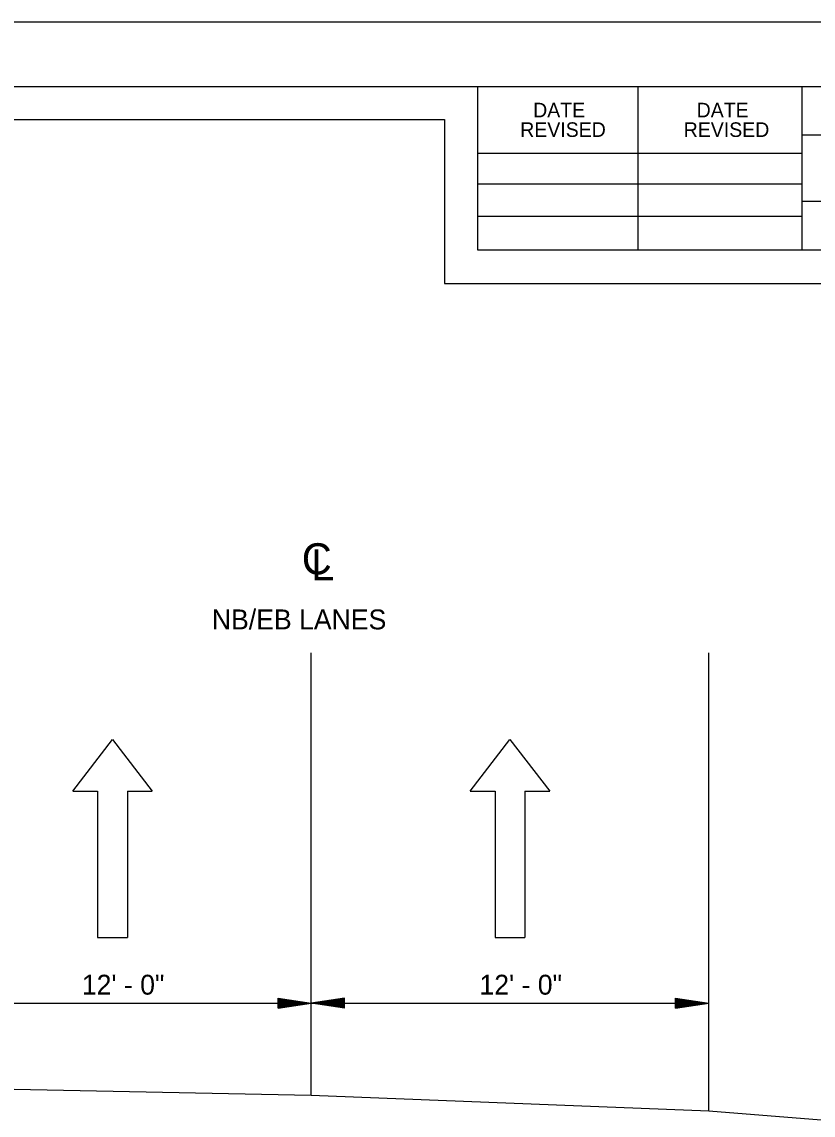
# Model space of a CAD drawing. Extents: x 1373889 to 1374222, y 382002 to 382215.
# Drawn here: x 1374127 to 1374174.7, y 382149.1 to 382215 of the extents above; entities that cross this region are included whole.
import ezdxf

# ---------------------------------------------------------------- set-up
doc = ezdxf.new("R2010")
doc.units = 0
for name, color, linetype in [('R_Border', 7, 'Continuous'), ('R_Draft', 7, 'Continuous'), ('R_No Plot', 7, 'Continuous'), ('R_Striping', 7, 'Continuous')]:
    doc.layers.add(name, color=color, linetype=linetype)

msp = doc.modelspace()

# ---------------------------------------------------------------- linework, layer by layer
at = {"layer": 'R_Border'}
for p, q in [((1373900.915, 382211.115), (1374217.095, 382211.115)), ((1374154.455, 382201.235), (1374154.455, 382211.115)), ((1374164.135, 382201.235), (1374164.135, 382211.115)), ((1374173.995, 382211.115), (1374173.995, 382201.235)), ((1374217.095, 382208.175), (1374173.995, 382208.175)), ((1374154.455, 382207.095), (1374173.995, 382207.095)), ((1374154.455, 382205.235), (1374173.995, 382205.235)), ((1374217.095, 382204.175), (1374173.995, 382204.175)), ((1374154.455, 382203.295), (1374173.995, 382203.295)), ((1374217.095, 382201.235), (1374154.455, 382201.235))]:
    msp.add_line(p, q, dxfattribs=at)
at = {"layer": 'R_Draft'}
for p, q in [((1374144.407, 382150.286), (1374144.407, 382176.948)), ((1374168.387, 382149.326), (1374168.387, 382176.948)), ((1374120.426, 382155.836), (1374144.407, 382155.836)), ((1374142.407, 382156.136), (1374144.407, 382155.836)), ((1374142.407, 382155.536), (1374142.407, 382156.136)), ((1374142.407, 382156.086), (1374144.073, 382155.836)), ((1374142.407, 382156.035), (1374143.729, 382155.836)), ((1374142.407, 382155.985), (1374143.396, 382155.836)), ((1374142.407, 382155.934), (1374143.057, 382155.836)), ((1374142.407, 382155.883), (1374142.723, 382155.836)), ((1374142.407, 382155.536), (1374144.407, 382155.836)), ((1374142.407, 382155.739), (1374143.057, 382155.836)), ((1374142.407, 382155.637), (1374143.729, 382155.836)), ((1374142.407, 382155.586), (1374144.073, 382155.836)), ((1374142.407, 382155.687), (1374143.396, 382155.836)), ((1374142.407, 382155.789), (1374142.723, 382155.836)), ((1374146.407, 382156.136), (1374144.407, 382155.836)), ((1374144.407, 382155.836), (1374168.387, 382155.836)), ((1374146.407, 382155.536), (1374144.407, 382155.836)), ((1374146.407, 382156.086), (1374144.741, 382155.836)), ((1374146.407, 382155.586), (1374144.741, 382155.836)), ((1374146.407, 382156.035), (1374145.085, 382155.836)), ((1374146.407, 382155.637), (1374145.085, 382155.836)), ((1374146.407, 382155.985), (1374145.418, 382155.836)), ((1374146.407, 382155.687), (1374145.418, 382155.836)), ((1374146.407, 382155.934), (1374145.757, 382155.836)), ((1374146.407, 382155.739), (1374145.757, 382155.836)), ((1374146.407, 382155.883), (1374146.091, 382155.836)), ((1374146.407, 382155.789), (1374146.091, 382155.836)), ((1374146.407, 382155.536), (1374146.407, 382156.136)), ((1374166.387, 382156.136), (1374168.387, 382155.836)), ((1374166.387, 382155.536), (1374166.387, 382156.136)), ((1374166.387, 382156.086), (1374168.053, 382155.836)), ((1374166.387, 382156.035), (1374167.709, 382155.836)), ((1374166.387, 382155.985), (1374167.376, 382155.836)), ((1374166.387, 382155.934), (1374167.037, 382155.836)), ((1374166.387, 382155.883), (1374166.703, 382155.836)), ((1374166.387, 382155.536), (1374168.387, 382155.836)), ((1374166.387, 382155.739), (1374167.037, 382155.836)), ((1374166.387, 382155.637), (1374167.709, 382155.836)), ((1374166.387, 382155.586), (1374168.053, 382155.836)), ((1374166.387, 382155.687), (1374167.376, 382155.836)), ((1374166.387, 382155.789), (1374166.703, 382155.836)), ((1374120.445, 382150.765), (1374144.407, 382150.286)), ((1374144.407, 382150.286), (1374168.387, 382149.326)), ((1374168.387, 382149.326), (1374188.411, 382147.721))]:
    msp.add_line(p, q, dxfattribs=at)
at = {"layer": 'R_No Plot'}
for points in [[(1373888.507, 382215.01), (1374221.847, 382215.01), (1374221.847, 382001.672), (1373888.507, 382001.672)], [(1374215.095, 382110.385), (1373902.915, 382110.385), (1373902.915, 382209.115), (1374152.455, 382209.115), (1374152.455, 382199.235), (1374169.995, 382199.235), (1374194.095, 382199.235), (1374194.095, 382176.903), (1374215.095, 382176.903)], [(1373902.915, 382209.115), (1374152.455, 382209.115), (1374152.455, 382199.235), (1374169.995, 382199.235), (1374194.095, 382199.235), (1374194.095, 382176.903), (1374215.095, 382176.903), (1374215.095, 382007.655), (1373902.915, 382007.655)]]:
    msp.add_lwpolyline(points, close=True, dxfattribs=at)
at = {"layer": 'R_Striping'}
for p, q in [((1374130.026, 382168.612), (1374132.426, 382171.728)), ((1374132.426, 382171.728), (1374134.826, 382168.612)), ((1374153.992, 382168.612), (1374156.392, 382171.728)), ((1374156.392, 382171.728), (1374158.792, 382168.612)), ((1374130.026, 382168.612), (1374131.526, 382168.612)), ((1374131.526, 382168.612), (1374131.526, 382159.785)), ((1374133.326, 382168.612), (1374133.326, 382159.785)), ((1374133.326, 382168.612), (1374134.826, 382168.612)), ((1374153.992, 382168.612), (1374155.492, 382168.612)), ((1374155.492, 382168.612), (1374155.492, 382159.785)), ((1374157.292, 382168.612), (1374157.292, 382159.785)), ((1374157.292, 382168.612), (1374158.792, 382168.612)), ((1374131.526, 382159.785), (1374133.326, 382159.785)), ((1374155.492, 382159.785), (1374157.292, 382159.785))]:
    msp.add_line(p, q, dxfattribs=at)

# ---------------------------------------------------------------- texts
at = {"layer": 'R_Border'}
for s, p in [('DATE', (1374157.793, 382209.251)), ('DATE', (1374167.653, 382209.251)), ('REVISED', (1374157.013, 382208.071)), ('REVISED', (1374166.873, 382208.071))]:
    msp.add_text(s, height=0.8792, dxfattribs=at).set_placement(p)
at = {"layer": 'R_Draft'}
for s, height, p in [('C', 1.875, (1374143.838, 382181.69)), ('L', 1.875, (1374144.405, 382181.322)), ('NB/EB LANES', 1.2, (1374138.414, 382178.371)), ('12\' - 0"', 1.2, (1374130.575, 382156.342)), ('12\' - 0"', 1.2, (1374154.555, 382156.342))]:
    msp.add_text(s, height=height, dxfattribs=at).set_placement(p)

doc.saveas('drawing.dxf')
